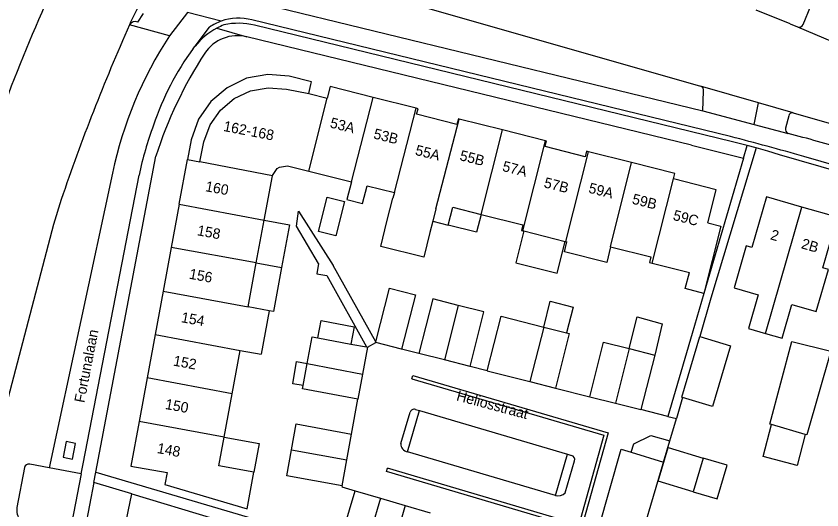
# Model space of a CAD drawing. Extents: x 194485 to 197793, y 468269 to 470822.
# Drawn here: x 195921.9 to 196015.1, y 469626 to 469683 of the extents above; entities that cross this region are included whole.
import ezdxf

# ---------------------------------------------------------------- set-up
doc = ezdxf.new("R2010")
doc.units = 0
for name, color, linetype in [('BGT begrenzing pand op maaiveld onder overbouw', 7, 'Continuous'), ('BGT grensvlak gebouwinstallatie plus 1', 7, 'Continuous'), ('BGT grensvlak pand deel overbouw', 7, 'Continuous'), ('BGT grensvlak pand op maaiveld', 7, 'Continuous'), ('BGT grensvlak pand op maaiveld LR', 7, 'Continuous'), ('BGT grensvlak wegdeel', 7, 'Continuous'), ('BGT tekst huisnummerreeks', 7, 'Continuous'), ('BGT tekst openbare ruimte label weg', 7, 'Continuous')]:
    doc.layers.add(name, color=color, linetype=linetype)

msp = doc.modelspace()

# ---------------------------------------------------------------- linework, layer by layer
at = {"layer": 'BGT begrenzing pand op maaiveld onder overbouw'}
msp.add_line((195941.686, 469666.469), (195943.146, 469666.188), dxfattribs=at)
msp.add_lwpolyline([(195943.146, 469666.188), (195943.588, 469668.494), (195944.309, 469670.467), (195945.53, 469672.176), (195947.088, 469673.515), (195948.986, 469674.392), (195951.046, 469674.759), (195953.136, 469674.615), (195955.722, 469674.079)], dxfattribs=at)
at = {"layer": 'BGT grensvlak gebouwinstallatie plus 1'}
for p, q in [((195949.664, 469654.512), (195952.577, 469653.974)), ((195982.909, 469647.099), (195983.653, 469650.074)), ((195983.653, 469650.074), (195986.299, 469649.391)), ((195986.299, 469649.391), (195985.526, 469646.436)), ((195956.784, 469645.835), (195957.175, 469647.867)), ((195957.175, 469647.867), (195960.974, 469647.137)), ((195992.783, 469644.605), (195993.695, 469648.263)), ((195993.695, 469648.263), (195996.611, 469647.476)), ((195996.611, 469647.476), (195995.742, 469643.856)), ((195960.974, 469647.137), (195960.589, 469645.135)), ((195953.901, 469640.523), (195954.329, 469643.127)), ((195954.329, 469643.127), (195955.561, 469642.906)), ((195955.087, 469640.328), (195953.901, 469640.523)), ((196008.293, 469632.134), (196009.26, 469635.825)), ((196013.147, 469634.685), (196012.21, 469631.108)), ((196012.21, 469631.108), (196008.293, 469632.134))]:
    msp.add_line(p, q, dxfattribs=at)
for points in [[(195959.861, 469661.608), (195958.864, 469657.631), (195956.84, 469658.139), (195957.838, 469662.115), (195959.861, 469661.608)], [(195975.66, 469660.122), (195975.143, 469658.071), (195971.87, 469658.896)], [(195950.576, 469659.454), (195953.489, 469658.916), (195952.577, 469653.974)], [(195980.596, 469658.204), (195979.675, 469654.525), (195984.461, 469653.326), (195985.382, 469657.005)], [(195952.577, 469653.974), (195951.637, 469648.882), (195951.133, 469648.975)], [(195945.946, 469634.374), (195949.977, 469633.63), (195949.366, 469630.318)], [(196000.181, 469628.064), (195996.14, 469629.27), (195997.302, 469633.166), (196001.344, 469631.96)]]:
    msp.add_lwpolyline(points, dxfattribs=at)
at = {"layer": 'BGT grensvlak pand deel overbouw'}
msp.add_lwpolyline([(195955.722, 469674.079), (195955.977, 469675.135), (195956.052, 469675.446), (195953.449, 469676.106), (195950.997, 469676.309), (195948.531, 469675.86), (195946.285, 469674.766), (195944.396, 469673.158), (195942.972, 469671.112), (195942.119, 469668.737), (195941.686, 469666.469)], dxfattribs=at)
at = {"layer": 'BGT grensvlak pand op maaiveld'}
for p, q in [((195955.722, 469674.079), (195957.84, 469673.543)), ((195968.153, 469672.397), (195963.169, 469673.653)), ((195978.121, 469669.885), (195973.137, 469671.141)), ((195983.105, 469668.628), (195978.121, 469669.885)), ((195993.073, 469666.115), (195988.089, 469667.372)), ((195940.733, 469661.299), (195941.686, 469666.469)), ((195955.72, 469665.132), (195960.657, 469663.888)), ((195950.576, 469659.454), (195951.523, 469664.582)), ((195965.632, 469662.635), (195965.453, 469661.999)), ((195964.775, 469659.292), (195965.453, 469661.999)), ((195940.733, 469661.299), (195939.809, 469656.279)), ((195949.664, 469654.512), (195950.576, 469659.454)), ((195970.066, 469659.348), (195969.741, 469658.048)), ((195970.066, 469659.348), (195971.87, 469658.896)), ((196003.402, 469658.747), (196001.43, 469650.995)), ((196001.88, 469659.134), (196003.402, 469658.747)), ((195980.484, 469658.232), (195980.596, 469658.204)), ((195980.596, 469658.204), (195985.382, 469657.005)), ((195985.289, 469655.794), (195985.58, 469656.955)), ((195985.382, 469657.005), (195985.47, 469656.983)), ((195985.47, 469656.983), (195985.58, 469656.955)), ((195939.809, 469656.279), (195938.882, 469651.253)), ((195990.188, 469654.567), (195985.289, 469655.794)), ((195990.639, 469656.368), (195990.188, 469654.567)), ((195948.724, 469649.42), (195949.664, 469654.512)), ((195995.442, 469654.484), (195999.746, 469653.405)), ((195999.273, 469651.544), (195999.746, 469653.405)), ((195938.882, 469651.253), (195937.957, 469646.228)), ((196001.43, 469650.995), (195999.273, 469651.544)), ((195951.133, 469648.975), (195948.724, 469649.42)), ((195951.133, 469648.975), (195950.211, 469643.96)), ((195982.909, 469647.099), (195985.526, 469646.436)), ((195937.957, 469646.228), (195937.034, 469641.222)), ((195956.784, 469645.835), (195960.589, 469645.135)), ((195960.589, 469645.135), (195962.417, 469644.799)), ((195962.515, 469644.781), (195961.943, 469641.673)), ((195962.417, 469644.799), (195962.515, 469644.781)), ((195963.467, 469645.311), (195963.491, 469645.407)), ((195946.872, 469639.389), (195947.798, 469644.405)), ((195947.798, 469644.405), (195950.211, 469643.96)), ((195971.414, 469643.309), (195968.463, 469644.056)), ((195992.783, 469644.605), (195995.742, 469643.856)), ((195995.742, 469643.856), (195994.147, 469637.555)), ((195955.087, 469640.328), (195955.561, 469642.906)), ((195974.378, 469642.558), (195971.414, 469643.309)), ((195976.357, 469642.052), (195981.301, 469640.801)), ((195937.034, 469641.222), (195936.108, 469636.196)), ((195961.943, 469641.673), (195961.411, 469638.779)), ((195981.301, 469640.801), (195984.261, 469640.051)), ((195945.946, 469634.374), (195946.872, 469639.389)), ((195988.231, 469639.051), (195991.19, 469638.303)), ((195991.19, 469638.303), (195994.147, 469637.555)), ((196013.147, 469634.685), (196009.26, 469635.825)), ((195945.334, 469631.062), (195945.946, 469634.374)), ((195960.119, 469631.734), (195960.665, 469634.735)), ((195959.574, 469628.733), (195960.119, 469631.734)), ((196001.344, 469631.96), (196000.181, 469628.064)), ((195949.366, 469630.318), (195945.334, 469631.062)), ((195959.275, 469622.034), (195961.086, 469628.172)), ((195961.086, 469628.172), (195964.011, 469627.309)), ((195935.264, 469627.818), (195944.713, 469624.981)), ((195964.011, 469627.309), (195966.889, 469626.46)), ((195966.889, 469626.46), (195969.766, 469625.611))]:
    msp.add_line(p, q, dxfattribs=at)
for points in [[(195963.169, 469673.653), (195958.185, 469674.91), (195957.84, 469673.543)], [(195973.137, 469671.141), (195973.031, 469671.168), (195972.869, 469670.528), (195968.205, 469671.703), (195968.366, 469672.343), (195968.153, 469672.397)], [(195988.089, 469667.372), (195987.866, 469667.428), (195987.705, 469666.788), (195983.051, 469667.961), (195983.212, 469668.601), (195983.105, 469668.628)], [(195997.9, 469664.218), (195998.061, 469664.858), (195993.073, 469666.115)], [(195951.523, 469664.582), (195951.529, 469664.613), (195952.066, 469665.423), (195952.336, 469665.594), (195953.286, 469665.746), (195955.72, 469665.132)], [(196001.88, 469659.134), (196002.849, 469662.945), (195997.9, 469664.218)], [(195960.657, 469663.888), (195960.144, 469661.852), (195961.955, 469661.385), (195962.471, 469663.431), (195965.632, 469662.635)], [(196012.766, 469660.967), (196008.663, 469662.151), (196006.953, 469656.312), (196006.328, 469656.492), (196004.914, 469651.641), (196007.709, 469650.837), (196006.58, 469646.928), (196008.553, 469646.364)], [(195971.87, 469658.896), (195972.383, 469660.943), (195975.66, 469660.122)], [(196008.553, 469646.364), (196010.497, 469645.809), (196011.617, 469649.714), (196014.412, 469648.911), (196015.827, 469653.755), (196015.202, 469653.935), (196016.87, 469659.783), (196012.766, 469660.967)], [(195975.66, 469660.122), (195980.502, 469658.908), (195980.342, 469658.268), (195980.484, 469658.232)], [(195969.741, 469658.048), (195969.022, 469655.181), (195964.056, 469656.425), (195964.775, 469659.292)], [(195990.639, 469656.368), (195995.304, 469655.199), (195995.144, 469654.559), (195995.442, 469654.484)], [(195963.491, 469645.407), (195965.064, 469651.606), (195968.069, 469650.843), (195966.472, 469644.551)], [(195973.021, 469649.607), (195970.059, 469650.357), (195968.463, 469644.056)], [(195974.378, 469642.558), (195975.974, 469648.859), (195973.021, 469649.607)], [(195976.357, 469642.052), (195977.966, 469648.354), (195982.909, 469647.099)], [(195955.561, 469642.906), (195956.122, 469645.957), (195956.784, 469645.835)], [(195985.526, 469646.436), (195985.858, 469646.352), (195984.261, 469640.051)], [(195998.949, 469638.963), (195998.859, 469638.99), (196000.944, 469646.004), (196000.964, 469645.998)], [(196000.964, 469645.998), (196004.502, 469644.946), (196002.417, 469637.932), (195998.949, 469638.963)], [(195966.472, 469644.551), (195966.47, 469644.542), (195963.467, 469645.311)], [(195988.231, 469639.051), (195989.826, 469645.353), (195992.783, 469644.605)], [(196009.26, 469635.825), (196009.052, 469635.886), (196011.581, 469645.445)], [(196011.581, 469645.445), (196016.109, 469644.331), (196013.342, 469634.628), (196013.147, 469634.685)], [(195961.411, 469638.779), (195955.018, 469639.955), (195955.087, 469640.328)], [(195936.108, 469636.196), (195935.158, 469631.039), (195939.346, 469630.269)], [(195953.73, 469632.924), (195954.27, 469635.897), (195960.665, 469634.735)], [(195959.574, 469628.733), (195953.179, 469629.895), (195953.73, 469632.924)], [(196000.181, 469628.064), (196002.969, 469627.232), (196004.132, 469631.128), (196001.344, 469631.96)], [(195939.346, 469630.269), (195939.091, 469628.883), (195948.586, 469626.091), (195949.366, 469630.318)], [(195932.813, 469618.796), (195933.778, 469623.862), (195934.412, 469623.745), (195935.264, 469627.818)]]:
    msp.add_lwpolyline(points, dxfattribs=at)
at = {"layer": 'BGT grensvlak pand op maaiveld LR'}
for p, q in [((195955.72, 469665.132), (195957.84, 469673.543)), ((195960.657, 469663.888), (195963.169, 469673.653)), ((195965.632, 469662.635), (195968.153, 469672.397)), ((195970.418, 469660.755), (195973.137, 469671.141)), ((195975.66, 469660.122), (195978.121, 469669.885)), ((195980.484, 469658.232), (195983.105, 469668.628)), ((195985.47, 469656.983), (195988.089, 469667.372)), ((195951.523, 469664.582), (195943.146, 469666.188)), ((195990.639, 469656.368), (195993.073, 469666.115)), ((195995.442, 469654.484), (195997.9, 469664.218)), ((195940.733, 469661.299), (195950.576, 469659.454)), ((195970.418, 469660.755), (195970.066, 469659.348)), ((196008.553, 469646.364), (196012.766, 469660.967)), ((195949.664, 469654.512), (195939.809, 469656.279)), ((195938.882, 469651.253), (195948.724, 469649.42)), ((195973.021, 469649.607), (195971.414, 469643.309)), ((195982.909, 469647.099), (195981.301, 469640.801)), ((195937.957, 469646.228), (195947.798, 469644.405)), ((195992.783, 469644.605), (195991.19, 469638.303)), ((195955.561, 469642.906), (195961.943, 469641.673)), ((195946.872, 469639.389), (195937.034, 469641.222)), ((195945.946, 469634.374), (195936.108, 469636.196)), ((195953.73, 469632.924), (195960.119, 469631.734)), ((195964.011, 469627.309), (195962.2, 469621.171)), ((195966.889, 469626.46), (195965.078, 469620.321))]:
    msp.add_line(p, q, dxfattribs=at)
at = {"layer": 'BGT grensvlak wegdeel'}
for p, q in [((195950.588, 469684.44), (196001.321, 469672.11)), ((196012.909, 469682.069), (196013.811, 469684.214)), ((195935.955, 469682.348), (195936.617, 469683.348)), ((195941.719, 469683.47), (195939.621, 469680.744)), ((195945.584, 469682.454), (195941.719, 469683.47)), ((196011.403, 469682.16), (196007.483, 469683.739)), ((195939.621, 469680.744), (195935, 469682.031)), ((196004.517, 469669.115), (195949.153, 469682.605)), ((196011.403, 469682.16), (196012.254, 469681.802)), ((195942.58, 469679.58), (195944.256, 469681.761)), ((195945.11, 469681.657), (195948.579, 469680.633)), ((196012.254, 469681.802), (196021.208, 469678.036)), ((196000, 469668.109), (195948.579, 469680.633)), ((195942.364, 469679.299), (195942.58, 469679.58)), ((196007.745, 469673.015), (196001.053, 469674.95)), ((196001.321, 469672.11), (196001.392, 469674.35)), ((196007.223, 469670.528), (196007.745, 469673.015)), ((196011.745, 469671.858), (196007.745, 469673.015)), ((196001.321, 469672.11), (196007.223, 469670.528)), ((196011.745, 469671.858), (196018.599, 469669.885)), ((196011.236, 469671.504), (196010.862, 469670.107)), ((196007.223, 469670.528), (196011.174, 469669.469)), ((196000, 469668.109), (196006.016, 469666.639)), ((196006.016, 469666.639), (196006.439, 469668.081)), ((196007.467, 469667.801), (196006.439, 469668.081)), ((196094.547, 469642.621), (196010.185, 469667.003)), ((195931.116, 469630.342), (195938.044, 469666.847)), ((196006.016, 469666.639), (196001.43, 469650.995)), ((195933.022, 469664.905), (195925.697, 469630.835)), ((195963.491, 469645.407), (195958.569, 469654.208)), ((195962.515, 469644.781), (195963.467, 469645.311)), ((195968.463, 469644.056), (195966.472, 469644.551)), ((195976.357, 469642.052), (195974.378, 469642.558)), ((195984.261, 469640.051), (195988.231, 469639.051)), ((195960.665, 469634.735), (195961.411, 469638.779)), ((195998.949, 469638.963), (195998.25, 469636.525)), ((195966.375, 469633.621), (195967.443, 469637.243)), ((195967.143, 469632.689), (195968.544, 469637.44)), ((195968.064, 469637.581), (195968.544, 469637.44)), ((195968.544, 469637.44), (195985.648, 469632.394)), ((195997.259, 469636.768), (195994.147, 469637.555)), ((195997.259, 469636.768), (195998.25, 469636.525)), ((195997.491, 469633.95), (195998.25, 469636.525)), ((195996.769, 469631.5), (195997.491, 469633.95)), ((195984.247, 469627.644), (195967.143, 469632.689)), ((195986.473, 469614.25), (195991.863, 469632.976)), ((195991.863, 469632.976), (195993.029, 469632.626)), ((195993.029, 469632.626), (195996.769, 469631.5)), ((195984.247, 469627.644), (195985.648, 469632.394)), ((195985.375, 469627.933), (195986.466, 469631.632)), ((195985.648, 469632.394), (195986.128, 469632.253)), ((195922.864, 469630.871), (195921.984, 469626.23)), ((195925.697, 469630.835), (195923.45, 469631.269)), ((195929.416, 469630.118), (195925.697, 469630.835)), ((195991.846, 469614.792), (195996.718, 469631.326)), ((195996.718, 469631.326), (195996.769, 469631.5)), ((195930.885, 469629.133), (195931.116, 469630.342)), ((195931.116, 469630.342), (195958.394, 469622.294)), ((195935.264, 469627.818), (195930.885, 469629.133)), ((195959.574, 469628.733), (195959.554, 469628.624)), ((195959.554, 469628.624), (195961.086, 469628.172))]:
    msp.add_line(p, q, dxfattribs=at)
for points in [[(195953.605, 469687.804), (195955.148, 469687.612), (195963.956, 469685.581), (196001.053, 469674.95)], [(196006.439, 469668.081), (196004.741, 469668.518), (195949.45, 469681.997)], [(196007.467, 469667.801), (196002.241, 469650.454), (196000.964, 469645.998)], [(196010.185, 469667.003), (196008.829, 469667.412), (196007.467, 469667.801)], [(196083.072, 469646.55), (196044.539, 469657.712), (196012.971, 469666.818)], [(195929.416, 469630.118), (195929.653, 469631.294), (195936.101, 469664.666)], [(195927.099, 469661.841), (195926.193, 469658.969), (195915.267, 469617.353), (195905.885, 469585.71), (195905.693, 469584.739)], [(195956.847, 469654.463), (195954.309, 469658.754), (195954.555, 469660.511), (195958.569, 469654.208)], [(195956.847, 469654.463), (195956.662, 469653.257), (195957.835, 469653.06), (195962.417, 469644.799)], [(196001.43, 469650.995), (196000.07, 469646.357), (195997.259, 469636.768)], [(195967.655, 469641.097), (195967.767, 469641.481), (195990.361, 469634.882), (195987.227, 469623.726), (195964.718, 469630.421), (195964.832, 469630.804)], [(195967.655, 469641.097), (195989.869, 469634.609), (195986.952, 469624.225), (195964.832, 469630.804)], [(195993.029, 469632.626), (195993.316, 469633.61), (195995.305, 469634.562), (195997.491, 469633.95)], [(195927.342, 469632.055), (195928.419, 469631.847), (195928.767, 469633.649), (195927.69, 469633.857), (195927.342, 469632.055)], [(195929.416, 469630.118), (195923.633, 469600.242), (195923.319, 469596.729), (195911.591, 469535.611)], [(195930.885, 469629.133), (195924.859, 469597.673), (195925.175, 469597.618), (195914.984, 469544.405), (195913.673, 469537.559)]]:
    msp.add_lwpolyline(points, dxfattribs=at)
for centre, radius, start, end in [((196130.285, 469593.728), 224.19, 155.93347, 159.70694), ((195946.898, 469677.402), 12.767, 146.39396, 158.74012), ((196149.273, 469586.538), 234.588, 155.97937, 161.2766), ((195935.652, 469681.664), 0.748, 66.09502, 150.63082), ((195947.62, 469676.933), 5.885, 110.24523, 124.86924), ((195948.802, 469674.595), 7.969, 111.17116, 117.60003), ((195947.604, 469676.972), 5.842, 74.6201, 110.22524), ((195947.625, 469674.514), 7.702, 76.29564, 102.76191), ((196012.448, 469682.263), 0.5, 247.19599, 337.15893), ((195948.827, 469674.55), 8.021, 117.61029, 141.15819), ((195978.882, 469655.093), 46.898, 146.84098, 167.92288), ((195947.463, 469676.258), 4.515, 75.68336, 146.44201), ((195968.409, 469660.2), 32.298, 143.74711, 161.53733), ((195985.595, 469651.556), 49.949, 147.00903, 162.17416), ((196000.899, 469674.467), 0.507, 346.60227, 72.33062), ((196011.681, 469671.407), 0.455, 81.92425, 167.71153), ((195976.988, 469655.918), 41.813, 159.69493, 167.9237), ((196011.39, 469669.97), 0.545, 165.42371, 246.69617), ((195928.973, 469374.372), 304.27, 73.97452, 75.62423), ((195979.764, 469544.327), 129.023, 72.78552, 75.90991), ((195967.922, 469637.102), 0.5, 73.50893, 163.60851), ((195967.286, 469633.589), 0.912, 178.00589, 260.97349), ((195985.985, 469631.773), 0.501, 343.66284, 73.4546), ((195923.357, 469630.775), 0.502, 79.33344, 169.03375), ((195984.594, 469628.636), 1.051, 250.71555, 318.02524), ((195923.788, 469625.909), 1.833, 169.91024, 217.7885)]:
    msp.add_arc(centre, radius, start, end, dxfattribs=at)

# ---------------------------------------------------------------- texts
at = {"layer": 'BGT tekst huisnummerreeks'}
for s, rotation, p in [('162-168', 349.1, (195945.791, 469669.773)), ('53A', 345.8, (195958.105, 469670.187)), ('53B', 345.9, (195963.135, 469668.916)), ('55A', 345.9, (195967.966, 469667.019)), ('55B', 345.9, (195973.103, 469666.404)), ('57A', 345.8, (195978.041, 469665.162)), ('57B', 345.9, (195982.851, 469663.266)), ('160', 349.6, (195943.699, 469662.814)), ('59A', 345.8, (195988.009, 469662.649)), ('59B', 345.9, (195993.041, 469661.378)), ('59C', 345.6, (195997.772, 469659.501)), ('158', 349.6, (195942.758, 469657.721)), ('2', 343.9, (196009.034, 469657.256)), ('2B', 343.9, (196012.601, 469656.227)), ('156', 349.5, (195941.832, 469652.698)), ('154', 349.6, (195940.91, 469647.671)), ('152', 349.6, (195939.989, 469642.654)), ('150', 349.6, (195939.061, 469637.639)), ('148', 349.6, (195938.12, 469632.549))]:
    msp.add_text(s, height=1.2, rotation=rotation, dxfattribs=at).set_placement(p)
at = {"layer": 'BGT tekst openbare ruimte label weg'}
for s, rotation, p in [('Fortunalaan', 79, (195929.775, 469638.281)), ('Heliosstraat', 345, (195972.728, 469638.636))]:
    msp.add_text(s, height=1.2, rotation=rotation, dxfattribs=at).set_placement(p)

doc.saveas('drawing.dxf')
